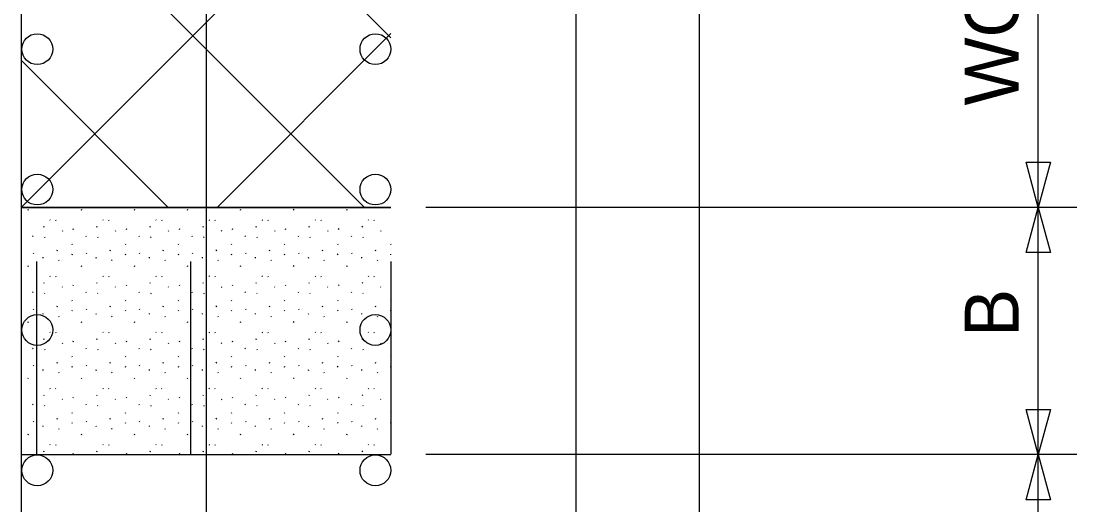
# Model space of a CAD drawing. Extents: x 16733 to 18475, y 5693 to 6915.
# Drawn here: x 17011.4 to 17148.4, y 6444 to 6506.8 of the extents above; entities that cross this region are included whole.
import ezdxf

# ---------------------------------------------------------------- set-up
doc = ezdxf.new("R2010")
doc.units = 0
for name, color, linetype in [('ALI_LEGAL_EX', 7, 'Continuous'), ('MT_SCRATCH_LEVEL_A', 7, 'Continuous'), ('PAVT_EDGE_EX', 7, 'Continuous'), ('TRAFFIC_SIGNS_PR', 7, 'Continuous'), ('TYPICAL_TEXT_DIMEN_PR', 7, 'Continuous')]:
    doc.layers.add(name, color=color, linetype=linetype)

msp = doc.modelspace()

# ---------------------------------------------------------------- linework, layer by layer
at = {"layer": 'ALI_LEGAL_EX'}
for points in [[(17013.43, 6475.6), (17013.43, 6450.6)], [(17033.43, 6475.6), (17033.43, 6450.6)], [(17059.43, 6475.6), (17059.43, 6450.6)]]:
    msp.add_lwpolyline(points, dxfattribs=at)
at = {"layer": 'MT_SCRATCH_LEVEL_A'}
for p, q in [((17011.43, 6628.39), (17011.43, 6450.54)), ((17011.43, 6596.33), (17011.43, 6482.6)), ((17059.43, 6504.61), (17011.43, 6552.61)), ((17011.43, 6482.6), (17059.43, 6530.6)), ((17055.98, 6482.6), (17011.43, 6527.15)), ((17036.89, 6482.6), (17059.43, 6505.15)), ((17030.53, 6482.6), (17011.43, 6501.69)), ((17011.43, 6482.6), (17059.43, 6482.6)), ((17011.43, 6482.6), (17059.43, 6482.6)), ((17059.43, 6482.6), (17011.43, 6482.6)), ((17011.43, 6482.6), (17011.43, 6450.54)), ((17011.43, 6482.6), (17011.43, 6482.6)), ((17012.36, 6482.24), (17012.41, 6482.36)), ((17019.25, 6482.24), (17019.3, 6482.36)), ((17026.14, 6482.24), (17026.19, 6482.36)), ((17033.02, 6482.24), (17033.08, 6482.36)), ((17039.91, 6482.24), (17039.96, 6482.36)), ((17046.8, 6482.24), (17046.85, 6482.36)), ((17053.69, 6482.24), (17053.74, 6482.36)), ((17014.38, 6480.05), (17014.43, 6480.16)), ((17015.15, 6481.01), (17015.2, 6480.93)), ((17015.88, 6480.98), (17015.93, 6480.9)), ((17021.27, 6480.05), (17021.32, 6480.16)), ((17022.03, 6481.01), (17022.08, 6480.93)), ((17022.77, 6480.98), (17022.82, 6480.9)), ((17028.16, 6480.05), (17028.21, 6480.16)), ((17028.92, 6481.01), (17028.97, 6480.93)), ((17029.66, 6480.98), (17029.71, 6480.9)), ((17035.04, 6480.05), (17035.1, 6480.16)), ((17035.81, 6481.01), (17035.86, 6480.93)), ((17036.55, 6480.98), (17036.6, 6480.9)), ((17041.93, 6480.05), (17041.98, 6480.16)), ((17042.69, 6481.01), (17042.75, 6480.93)), ((17043.43, 6480.98), (17043.48, 6480.9)), ((17048.82, 6480.05), (17048.87, 6480.16)), ((17049.58, 6481.01), (17049.63, 6480.93)), ((17050.32, 6480.98), (17050.37, 6480.9)), ((17055.71, 6480.05), (17055.76, 6480.16)), ((17056.47, 6481.01), (17056.52, 6480.93)), ((17057.21, 6480.98), (17057.26, 6480.9)), ((17012.93, 6478.92), (17012.98, 6478.84)), ((17014.46, 6478.78), (17014.51, 6478.7)), ((17016.75, 6479.6), (17016.8, 6479.52)), ((17018.2, 6479.75), (17018.25, 6479.87)), ((17019.82, 6478.92), (17019.87, 6478.84)), ((17021.35, 6478.78), (17021.4, 6478.7)), ((17023.64, 6479.6), (17023.69, 6479.52)), ((17025.09, 6479.75), (17025.14, 6479.87)), ((17026.71, 6478.92), (17026.76, 6478.84)), ((17028.24, 6478.78), (17028.29, 6478.7)), ((17030.53, 6479.6), (17030.58, 6479.52)), ((17031.97, 6479.75), (17032.03, 6479.87)), ((17033.59, 6478.92), (17033.65, 6478.84)), ((17035.12, 6478.78), (17035.17, 6478.7)), ((17037.41, 6479.6), (17037.47, 6479.52)), ((17038.86, 6479.75), (17038.91, 6479.87)), ((17040.48, 6478.92), (17040.53, 6478.84)), ((17042.01, 6478.78), (17042.06, 6478.7)), ((17044.3, 6479.6), (17044.35, 6479.52)), ((17045.75, 6479.75), (17045.8, 6479.87)), ((17047.37, 6478.92), (17047.42, 6478.84)), ((17048.9, 6478.78), (17048.95, 6478.7)), ((17051.19, 6479.6), (17051.24, 6479.52)), ((17052.64, 6479.75), (17052.69, 6479.87)), ((17054.26, 6478.92), (17054.31, 6478.84)), ((17055.79, 6478.78), (17055.84, 6478.7)), ((17058.08, 6479.6), (17058.13, 6479.52)), ((17018.03, 6477.86), (17018.08, 6477.78)), ((17024.92, 6477.86), (17024.97, 6477.78)), ((17031.8, 6477.86), (17031.85, 6477.78)), ((17038.69, 6477.86), (17038.74, 6477.78)), ((17045.58, 6477.86), (17045.63, 6477.78)), ((17052.47, 6477.86), (17052.52, 6477.78)), ((17059.35, 6477.86), (17059.4, 6477.78)), ((17012.98, 6476.71), (17013.03, 6476.64)), ((17014.26, 6476.14), (17014.27, 6476.02)), ((17016.1, 6476.99), (17016.15, 6477.11)), ((17018.07, 6476.46), (17018.12, 6476.58)), ((17019.87, 6476.71), (17019.92, 6476.64)), ((17021.15, 6476.14), (17021.16, 6476.02)), ((17022.99, 6476.99), (17023.04, 6477.11)), ((17024.96, 6476.46), (17025.01, 6476.58)), ((17026.76, 6476.71), (17026.81, 6476.64)), ((17028.04, 6476.14), (17028.05, 6476.02)), ((17029.88, 6476.99), (17029.93, 6477.11)), ((17031.85, 6476.46), (17031.9, 6476.58)), ((17033.64, 6476.71), (17033.69, 6476.64)), ((17034.92, 6476.14), (17034.94, 6476.02)), ((17036.76, 6476.99), (17036.82, 6477.11)), ((17038.73, 6476.46), (17038.78, 6476.58)), ((17040.53, 6476.71), (17040.58, 6476.64)), ((17041.81, 6476.14), (17041.82, 6476.02)), ((17043.65, 6476.99), (17043.7, 6477.11)), ((17045.62, 6476.46), (17045.67, 6476.58)), ((17047.42, 6476.71), (17047.47, 6476.64)), ((17048.7, 6476.14), (17048.71, 6476.02)), ((17050.54, 6476.99), (17050.59, 6477.11)), ((17052.51, 6476.46), (17052.56, 6476.58)), ((17054.31, 6476.71), (17054.36, 6476.64)), ((17055.59, 6476.14), (17055.6, 6476.02)), ((17057.43, 6476.99), (17057.48, 6477.11)), ((17059.4, 6476.46), (17059.43, 6476.55)), ((17012.36, 6474.96), (17012.41, 6475.08)), ((17016.29, 6475.79), (17016.34, 6475.72)), ((17019.25, 6474.96), (17019.3, 6475.08)), ((17023.18, 6475.79), (17023.23, 6475.72)), ((17026.14, 6474.96), (17026.19, 6475.08)), ((17030.07, 6475.79), (17030.12, 6475.72)), ((17033.02, 6474.96), (17033.08, 6475.08)), ((17036.95, 6475.79), (17037.01, 6475.72)), ((17039.91, 6474.96), (17039.96, 6475.08)), ((17043.84, 6475.79), (17043.89, 6475.72)), ((17046.8, 6474.96), (17046.85, 6475.08)), ((17050.73, 6475.79), (17050.78, 6475.72)), ((17053.69, 6474.96), (17053.74, 6475.08)), ((17057.62, 6475.79), (17057.67, 6475.72)), ((17015.15, 6473.72), (17015.2, 6473.65)), ((17015.88, 6473.69), (17015.93, 6473.62)), ((17022.03, 6473.72), (17022.08, 6473.65)), ((17022.77, 6473.69), (17022.82, 6473.62)), ((17028.92, 6473.72), (17028.97, 6473.65)), ((17029.66, 6473.69), (17029.71, 6473.62)), ((17035.81, 6473.72), (17035.86, 6473.65)), ((17036.55, 6473.69), (17036.6, 6473.62)), ((17042.69, 6473.72), (17042.75, 6473.65)), ((17043.43, 6473.69), (17043.48, 6473.62)), ((17049.58, 6473.72), (17049.63, 6473.65)), ((17050.32, 6473.69), (17050.37, 6473.62)), ((17056.47, 6473.72), (17056.52, 6473.65)), ((17057.21, 6473.69), (17057.26, 6473.62)), ((17014.38, 6472.76), (17014.43, 6472.88)), ((17016.75, 6472.31), (17016.8, 6472.24)), ((17018.2, 6472.47), (17018.25, 6472.58)), ((17021.27, 6472.76), (17021.32, 6472.88)), ((17023.64, 6472.31), (17023.69, 6472.24)), ((17025.09, 6472.47), (17025.14, 6472.58)), ((17028.16, 6472.76), (17028.21, 6472.88)), ((17030.53, 6472.31), (17030.58, 6472.24)), ((17031.97, 6472.47), (17032.03, 6472.58)), ((17035.04, 6472.76), (17035.1, 6472.88)), ((17037.41, 6472.31), (17037.47, 6472.24)), ((17038.86, 6472.47), (17038.91, 6472.58)), ((17041.93, 6472.76), (17041.98, 6472.88)), ((17044.3, 6472.31), (17044.35, 6472.24)), ((17045.75, 6472.47), (17045.8, 6472.58)), ((17048.82, 6472.76), (17048.87, 6472.88)), ((17051.19, 6472.31), (17051.24, 6472.24)), ((17052.64, 6472.47), (17052.69, 6472.58)), ((17055.71, 6472.76), (17055.76, 6472.88)), ((17058.08, 6472.31), (17058.13, 6472.24)), ((17012.93, 6471.64), (17012.98, 6471.56)), ((17014.46, 6471.5), (17014.51, 6471.42)), ((17018.03, 6470.58), (17018.08, 6470.5)), ((17019.82, 6471.64), (17019.87, 6471.56)), ((17021.35, 6471.5), (17021.4, 6471.42)), ((17024.92, 6470.58), (17024.97, 6470.5)), ((17026.71, 6471.64), (17026.76, 6471.56)), ((17028.24, 6471.5), (17028.29, 6471.42)), ((17031.8, 6470.58), (17031.85, 6470.5)), ((17033.59, 6471.64), (17033.65, 6471.56)), ((17035.12, 6471.5), (17035.17, 6471.42)), ((17038.69, 6470.58), (17038.74, 6470.5)), ((17040.48, 6471.64), (17040.53, 6471.56)), ((17042.01, 6471.5), (17042.06, 6471.42)), ((17045.58, 6470.58), (17045.63, 6470.5)), ((17047.37, 6471.64), (17047.42, 6471.56)), ((17048.9, 6471.5), (17048.95, 6471.42)), ((17052.47, 6470.58), (17052.52, 6470.5)), ((17054.26, 6471.64), (17054.31, 6471.56)), ((17055.79, 6471.5), (17055.84, 6471.42)), ((17059.35, 6470.58), (17059.4, 6470.5)), ((17012.98, 6469.43), (17013.03, 6469.35)), ((17016.1, 6469.71), (17016.15, 6469.82)), ((17018.07, 6469.18), (17018.12, 6469.29)), ((17019.87, 6469.43), (17019.92, 6469.35)), ((17022.99, 6469.71), (17023.04, 6469.82)), ((17024.96, 6469.18), (17025.01, 6469.29)), ((17026.76, 6469.43), (17026.81, 6469.35)), ((17029.88, 6469.71), (17029.93, 6469.82)), ((17031.85, 6469.18), (17031.9, 6469.29)), ((17033.64, 6469.43), (17033.69, 6469.35)), ((17036.76, 6469.71), (17036.82, 6469.82)), ((17038.73, 6469.18), (17038.78, 6469.29)), ((17040.53, 6469.43), (17040.58, 6469.35)), ((17043.65, 6469.71), (17043.7, 6469.82)), ((17045.62, 6469.18), (17045.67, 6469.29)), ((17047.42, 6469.43), (17047.47, 6469.35)), ((17050.54, 6469.71), (17050.59, 6469.82)), ((17052.51, 6469.18), (17052.56, 6469.29)), ((17054.31, 6469.43), (17054.36, 6469.35)), ((17057.43, 6469.71), (17057.48, 6469.82)), ((17059.4, 6469.18), (17059.43, 6469.26)), ((17012.36, 6467.68), (17012.41, 6467.79)), ((17014.26, 6468.85), (17014.27, 6468.74)), ((17016.29, 6468.51), (17016.34, 6468.43)), ((17019.25, 6467.68), (17019.3, 6467.79)), ((17021.15, 6468.85), (17021.16, 6468.74)), ((17023.18, 6468.51), (17023.23, 6468.43)), ((17026.14, 6467.68), (17026.19, 6467.79)), ((17028.04, 6468.85), (17028.05, 6468.74)), ((17030.07, 6468.51), (17030.12, 6468.43)), ((17033.02, 6467.68), (17033.08, 6467.79)), ((17034.92, 6468.85), (17034.94, 6468.74)), ((17036.95, 6468.51), (17037.01, 6468.43)), ((17039.91, 6467.68), (17039.96, 6467.79)), ((17041.81, 6468.85), (17041.82, 6468.74)), ((17043.84, 6468.51), (17043.89, 6468.43)), ((17046.8, 6467.68), (17046.85, 6467.79)), ((17048.7, 6468.85), (17048.71, 6468.74)), ((17050.73, 6468.51), (17050.78, 6468.43)), ((17053.69, 6467.68), (17053.74, 6467.79)), ((17055.59, 6468.85), (17055.6, 6468.74)), ((17057.62, 6468.51), (17057.67, 6468.43)), ((17015.15, 6466.44), (17015.2, 6466.36)), ((17015.88, 6466.41), (17015.93, 6466.33)), ((17022.03, 6466.44), (17022.08, 6466.36)), ((17022.77, 6466.41), (17022.82, 6466.33)), ((17028.92, 6466.44), (17028.97, 6466.36)), ((17029.66, 6466.41), (17029.71, 6466.33)), ((17035.81, 6466.44), (17035.86, 6466.36)), ((17036.55, 6466.41), (17036.6, 6466.33)), ((17042.69, 6466.44), (17042.75, 6466.36)), ((17043.43, 6466.41), (17043.48, 6466.33)), ((17049.58, 6466.44), (17049.63, 6466.36)), ((17050.32, 6466.41), (17050.37, 6466.33)), ((17056.47, 6466.44), (17056.52, 6466.36)), ((17057.21, 6466.41), (17057.26, 6466.33)), ((17014.38, 6465.48), (17014.43, 6465.6)), ((17018.2, 6465.18), (17018.25, 6465.3)), ((17021.27, 6465.48), (17021.32, 6465.6)), ((17025.09, 6465.18), (17025.14, 6465.3)), ((17028.16, 6465.48), (17028.21, 6465.6)), ((17031.97, 6465.18), (17032.03, 6465.3)), ((17035.04, 6465.48), (17035.1, 6465.6)), ((17038.86, 6465.18), (17038.91, 6465.3)), ((17041.93, 6465.48), (17041.98, 6465.6)), ((17045.75, 6465.18), (17045.8, 6465.3)), ((17048.82, 6465.48), (17048.87, 6465.6)), ((17052.64, 6465.18), (17052.69, 6465.3)), ((17055.71, 6465.48), (17055.76, 6465.6)), ((17012.93, 6464.35), (17012.98, 6464.28)), ((17014.46, 6464.21), (17014.51, 6464.13)), ((17016.75, 6465.03), (17016.8, 6464.95)), ((17019.82, 6464.35), (17019.87, 6464.28)), ((17021.35, 6464.21), (17021.4, 6464.13)), ((17023.64, 6465.03), (17023.69, 6464.95)), ((17026.71, 6464.35), (17026.76, 6464.28)), ((17028.24, 6464.21), (17028.29, 6464.13)), ((17030.53, 6465.03), (17030.58, 6464.95)), ((17033.59, 6464.35), (17033.65, 6464.28)), ((17035.12, 6464.21), (17035.17, 6464.13)), ((17037.41, 6465.03), (17037.47, 6464.95)), ((17040.48, 6464.35), (17040.53, 6464.28)), ((17042.01, 6464.21), (17042.06, 6464.13)), ((17044.3, 6465.03), (17044.35, 6464.95)), ((17047.37, 6464.35), (17047.42, 6464.28)), ((17048.9, 6464.21), (17048.95, 6464.13)), ((17051.19, 6465.03), (17051.24, 6464.95)), ((17054.26, 6464.35), (17054.31, 6464.28)), ((17055.79, 6464.21), (17055.84, 6464.13)), ((17058.08, 6465.03), (17058.13, 6464.95)), ((17016.1, 6462.42), (17016.15, 6462.54)), ((17018.03, 6463.29), (17018.08, 6463.22)), ((17022.99, 6462.42), (17023.04, 6462.54)), ((17024.92, 6463.29), (17024.97, 6463.22)), ((17029.88, 6462.42), (17029.93, 6462.54)), ((17031.8, 6463.29), (17031.85, 6463.22)), ((17036.76, 6462.42), (17036.82, 6462.54)), ((17038.69, 6463.29), (17038.74, 6463.22)), ((17043.65, 6462.42), (17043.7, 6462.54)), ((17045.58, 6463.29), (17045.63, 6463.22)), ((17050.54, 6462.42), (17050.59, 6462.54)), ((17052.47, 6463.29), (17052.52, 6463.22)), ((17057.43, 6462.42), (17057.48, 6462.54)), ((17059.35, 6463.29), (17059.4, 6463.22)), ((17012.98, 6462.14), (17013.03, 6462.07)), ((17014.26, 6461.57), (17014.27, 6461.45)), ((17016.29, 6461.22), (17016.34, 6461.15)), ((17018.07, 6461.89), (17018.12, 6462.01)), ((17019.87, 6462.14), (17019.92, 6462.07)), ((17021.15, 6461.57), (17021.16, 6461.45)), ((17023.18, 6461.22), (17023.23, 6461.15)), ((17024.96, 6461.89), (17025.01, 6462.01)), ((17026.76, 6462.14), (17026.81, 6462.07)), ((17028.04, 6461.57), (17028.05, 6461.45)), ((17030.07, 6461.22), (17030.12, 6461.15)), ((17031.85, 6461.89), (17031.9, 6462.01)), ((17033.64, 6462.14), (17033.69, 6462.07)), ((17034.92, 6461.57), (17034.94, 6461.45)), ((17036.95, 6461.22), (17037.01, 6461.15)), ((17038.73, 6461.89), (17038.78, 6462.01)), ((17040.53, 6462.14), (17040.58, 6462.07)), ((17041.81, 6461.57), (17041.82, 6461.45)), ((17043.84, 6461.22), (17043.89, 6461.15)), ((17045.62, 6461.89), (17045.67, 6462.01)), ((17047.42, 6462.14), (17047.47, 6462.07)), ((17048.7, 6461.57), (17048.71, 6461.45)), ((17050.73, 6461.22), (17050.78, 6461.15)), ((17052.51, 6461.89), (17052.56, 6462.01)), ((17054.31, 6462.14), (17054.36, 6462.07)), ((17055.59, 6461.57), (17055.6, 6461.45)), ((17057.62, 6461.22), (17057.67, 6461.15)), ((17059.4, 6461.89), (17059.43, 6461.98)), ((17012.36, 6460.39), (17012.41, 6460.51)), ((17019.25, 6460.39), (17019.3, 6460.51)), ((17026.14, 6460.39), (17026.19, 6460.51)), ((17033.02, 6460.39), (17033.08, 6460.51)), ((17039.91, 6460.39), (17039.96, 6460.51)), ((17046.8, 6460.39), (17046.85, 6460.51)), ((17053.69, 6460.39), (17053.74, 6460.51)), ((17014.38, 6458.19), (17014.43, 6458.31)), ((17015.15, 6459.15), (17015.2, 6459.08)), ((17015.88, 6459.12), (17015.93, 6459.05)), ((17021.27, 6458.19), (17021.32, 6458.31)), ((17022.03, 6459.15), (17022.08, 6459.08)), ((17022.77, 6459.12), (17022.82, 6459.05)), ((17028.16, 6458.19), (17028.21, 6458.31)), ((17028.92, 6459.15), (17028.97, 6459.08)), ((17029.66, 6459.12), (17029.71, 6459.05)), ((17035.04, 6458.19), (17035.1, 6458.31)), ((17035.81, 6459.15), (17035.86, 6459.08)), ((17036.55, 6459.12), (17036.6, 6459.05)), ((17041.93, 6458.19), (17041.98, 6458.31)), ((17042.69, 6459.15), (17042.75, 6459.08)), ((17043.43, 6459.12), (17043.48, 6459.05)), ((17048.82, 6458.19), (17048.87, 6458.31)), ((17049.58, 6459.15), (17049.63, 6459.08)), ((17050.32, 6459.12), (17050.37, 6459.05)), ((17055.71, 6458.19), (17055.76, 6458.31)), ((17056.47, 6459.15), (17056.52, 6459.08)), ((17057.21, 6459.12), (17057.26, 6459.05)), ((17012.93, 6457.07), (17012.98, 6456.99)), ((17014.46, 6456.93), (17014.51, 6456.85)), ((17016.75, 6457.74), (17016.8, 6457.67)), ((17018.2, 6457.9), (17018.25, 6458.01)), ((17019.82, 6457.07), (17019.87, 6456.99)), ((17021.35, 6456.93), (17021.4, 6456.85)), ((17023.64, 6457.74), (17023.69, 6457.67)), ((17025.09, 6457.9), (17025.14, 6458.01)), ((17026.71, 6457.07), (17026.76, 6456.99)), ((17028.24, 6456.93), (17028.29, 6456.85)), ((17030.53, 6457.74), (17030.58, 6457.67)), ((17031.97, 6457.9), (17032.03, 6458.01)), ((17033.59, 6457.07), (17033.65, 6456.99)), ((17035.12, 6456.93), (17035.17, 6456.85)), ((17037.41, 6457.74), (17037.47, 6457.67)), ((17038.86, 6457.9), (17038.91, 6458.01)), ((17040.48, 6457.07), (17040.53, 6456.99)), ((17042.01, 6456.93), (17042.06, 6456.85)), ((17044.3, 6457.74), (17044.35, 6457.67)), ((17045.75, 6457.9), (17045.8, 6458.01)), ((17047.37, 6457.07), (17047.42, 6456.99)), ((17048.9, 6456.93), (17048.95, 6456.85)), ((17051.19, 6457.74), (17051.24, 6457.67)), ((17052.64, 6457.9), (17052.69, 6458.01)), ((17054.26, 6457.07), (17054.31, 6456.99)), ((17055.79, 6456.93), (17055.84, 6456.85)), ((17058.08, 6457.74), (17058.13, 6457.67)), ((17018.03, 6456.01), (17018.08, 6455.93)), ((17024.92, 6456.01), (17024.97, 6455.93)), ((17031.8, 6456.01), (17031.85, 6455.93)), ((17038.69, 6456.01), (17038.74, 6455.93)), ((17045.58, 6456.01), (17045.63, 6455.93)), ((17052.47, 6456.01), (17052.52, 6455.93)), ((17059.35, 6456.01), (17059.4, 6455.93)), ((17012.98, 6454.86), (17013.03, 6454.78)), ((17014.26, 6454.28), (17014.27, 6454.17)), ((17016.1, 6455.14), (17016.15, 6455.26)), ((17018.07, 6454.61), (17018.12, 6454.72)), ((17019.87, 6454.86), (17019.92, 6454.78)), ((17021.15, 6454.28), (17021.16, 6454.17)), ((17022.99, 6455.14), (17023.04, 6455.26)), ((17024.96, 6454.61), (17025.01, 6454.72)), ((17026.76, 6454.86), (17026.81, 6454.78)), ((17028.04, 6454.28), (17028.05, 6454.17)), ((17029.88, 6455.14), (17029.93, 6455.26)), ((17031.85, 6454.61), (17031.9, 6454.72)), ((17033.64, 6454.86), (17033.69, 6454.78)), ((17034.92, 6454.28), (17034.94, 6454.17)), ((17036.76, 6455.14), (17036.82, 6455.26)), ((17038.73, 6454.61), (17038.78, 6454.72)), ((17040.53, 6454.86), (17040.58, 6454.78)), ((17041.81, 6454.28), (17041.82, 6454.17)), ((17043.65, 6455.14), (17043.7, 6455.26)), ((17045.62, 6454.61), (17045.67, 6454.72)), ((17047.42, 6454.86), (17047.47, 6454.78)), ((17048.7, 6454.28), (17048.71, 6454.17)), ((17050.54, 6455.14), (17050.59, 6455.26)), ((17052.51, 6454.61), (17052.56, 6454.72)), ((17054.31, 6454.86), (17054.36, 6454.78)), ((17055.59, 6454.28), (17055.6, 6454.17)), ((17057.43, 6455.14), (17057.48, 6455.26)), ((17059.4, 6454.61), (17059.43, 6454.69)), ((17012.36, 6453.11), (17012.41, 6453.22)), ((17016.29, 6453.94), (17016.34, 6453.86)), ((17019.25, 6453.11), (17019.3, 6453.22)), ((17023.18, 6453.94), (17023.23, 6453.86)), ((17026.14, 6453.11), (17026.19, 6453.22)), ((17030.07, 6453.94), (17030.12, 6453.86)), ((17033.02, 6453.11), (17033.08, 6453.22)), ((17036.95, 6453.94), (17037.01, 6453.86)), ((17039.91, 6453.11), (17039.96, 6453.22)), ((17043.84, 6453.94), (17043.89, 6453.86)), ((17046.8, 6453.11), (17046.85, 6453.22)), ((17050.73, 6453.94), (17050.78, 6453.86)), ((17053.69, 6453.11), (17053.74, 6453.22)), ((17057.62, 6453.94), (17057.67, 6453.86)), ((17015.15, 6451.87), (17015.2, 6451.79)), ((17015.88, 6451.84), (17015.93, 6451.76)), ((17022.03, 6451.87), (17022.08, 6451.79)), ((17022.77, 6451.84), (17022.82, 6451.76)), ((17028.92, 6451.87), (17028.97, 6451.79)), ((17029.66, 6451.84), (17029.71, 6451.76)), ((17035.81, 6451.87), (17035.86, 6451.79)), ((17036.55, 6451.84), (17036.6, 6451.76)), ((17042.69, 6451.87), (17042.75, 6451.79)), ((17043.43, 6451.84), (17043.48, 6451.76)), ((17049.58, 6451.87), (17049.63, 6451.79)), ((17050.32, 6451.84), (17050.37, 6451.76)), ((17056.47, 6451.87), (17056.52, 6451.79)), ((17057.21, 6451.84), (17057.26, 6451.76)), ((17011.43, 6450.54), (17059.43, 6450.54)), ((17011.43, 6450.54), (17059.43, 6450.54)), ((17014.38, 6450.91), (17014.43, 6451.03)), ((17018.2, 6450.61), (17018.25, 6450.73)), ((17021.27, 6450.91), (17021.32, 6451.03)), ((17025.09, 6450.61), (17025.14, 6450.73)), ((17028.16, 6450.91), (17028.21, 6451.03)), ((17031.97, 6450.61), (17032.03, 6450.73)), ((17035.04, 6450.91), (17035.1, 6451.03)), ((17038.86, 6450.61), (17038.91, 6450.73)), ((17041.93, 6450.91), (17041.98, 6451.03)), ((17045.75, 6450.61), (17045.8, 6450.73)), ((17048.82, 6450.91), (17048.87, 6451.03)), ((17052.64, 6450.61), (17052.69, 6450.73)), ((17055.71, 6450.91), (17055.76, 6451.03))]:
    msp.add_line(p, q, dxfattribs=at)
at = {"layer": 'PAVT_EDGE_EX'}
for p, q in [((17011.43, 6893.09), (17011.43, 6095.81)), ((17035.43, 6893.09), (17035.43, 6095.81)), ((17083.43, 6893.09), (17083.43, 6095.81)), ((17099.43, 6893.09), (17099.43, 6095.81))]:
    msp.add_line(p, q, dxfattribs=at)
at = {"layer": 'TRAFFIC_SIGNS_PR'}
for centre in [(17013.53, 6503.13), (17057.41, 6503.13), (17013.53, 6484.92), (17057.41, 6484.92), (17013.53, 6466.71), (17057.41, 6466.71), (17013.53, 6448.49), (17057.41, 6448.49)]:
    msp.add_circle(centre, 2, dxfattribs=at)
at = {"layer": 'TYPICAL_TEXT_DIMEN_PR'}
for p, q in [((17143.43, 6482.6), (17143.43, 6596.33)), ((17143.43, 6482.6), (17141.86, 6488.47)), ((17141.86, 6488.47), (17143.43, 6488.47)), ((17143.43, 6488.47), (17145, 6488.47)), ((17145, 6488.47), (17143.43, 6482.6)), ((17148.43, 6482.6), (17063.94, 6482.6)), ((17141.86, 6476.74), (17143.43, 6482.6)), ((17143.43, 6450.54), (17143.43, 6482.6)), ((17143.43, 6482.6), (17145, 6476.74)), ((17143.43, 6476.74), (17141.86, 6476.74)), ((17145, 6476.74), (17143.43, 6476.74)), ((17143.43, 6450.54), (17141.86, 6456.41)), ((17141.86, 6456.41), (17143.43, 6456.41)), ((17143.43, 6456.41), (17145, 6456.41)), ((17145, 6456.41), (17143.43, 6450.54)), ((17148.43, 6450.54), (17063.94, 6450.54)), ((17141.86, 6444.68), (17143.43, 6450.54)), ((17143.43, 6450.54), (17145, 6444.68)), ((17143.43, 6419.97), (17143.43, 6450.54)), ((17143.43, 6444.68), (17141.86, 6444.68)), ((17145, 6444.68), (17143.43, 6444.68))]:
    msp.add_line(p, q, dxfattribs=at)

# ---------------------------------------------------------------- texts
for s, p in [('WORK AREA VARIES', (17140.88, 6495.82)), ('B', (17140.88, 6465.81))]:
    msp.add_text(s, height=7, rotation=90, dxfattribs=at).set_placement(p)

doc.saveas('drawing.dxf')
